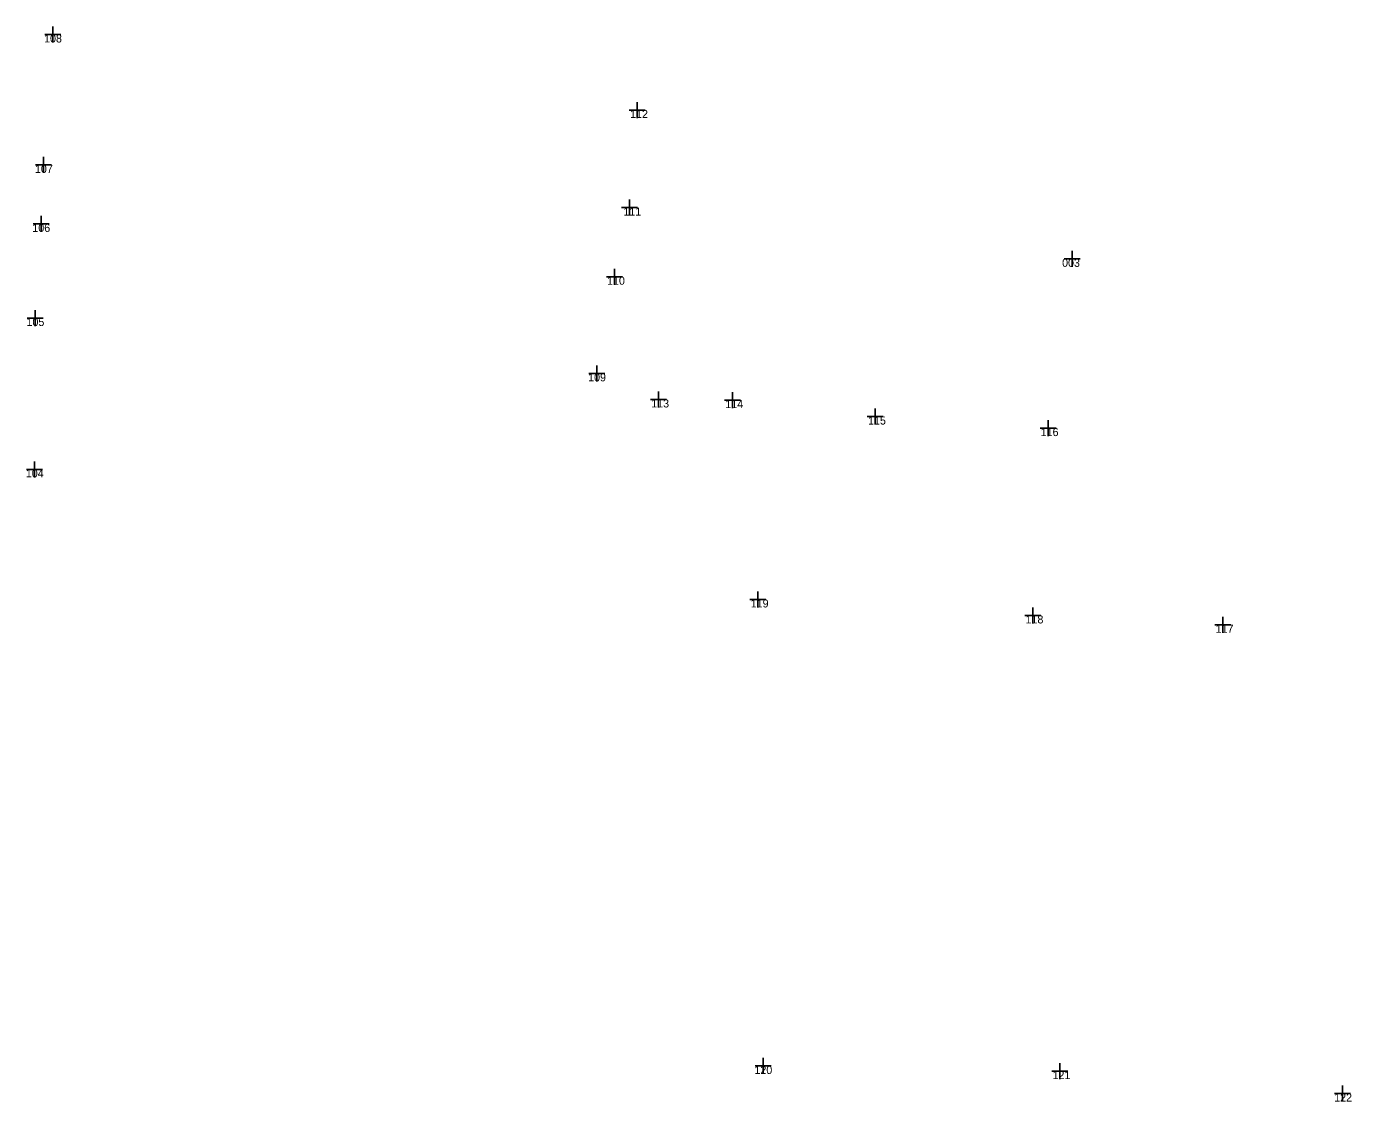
# Model space of a CAD drawing. Extents: x -706655 to -706193, y -1036183 to -1034979.
# Drawn here: x -706282.4 to -706199.6, y -1035570.8 to -1035503.7 of the extents above; entities that cross this region are included whole.
import ezdxf

# ---------------------------------------------------------------- set-up
doc = ezdxf.new("R2010")
doc.units = 0
doc.layers.add('čísla bodu', color=7, linetype='Continuous')

msp = doc.modelspace()

# ---------------------------------------------------------------- linework, layer by layer
at = {"layer": 'čísla bodu'}
for p, q in [((-706281.25, -1035504.15), (-706280.25, -1035504.15)), ((-706280.75, -1035504.65), (-706280.75, -1035503.65)), ((-706280.75, -1035504.15), (-706280.75, -1035504.15)), ((-706244.22, -1035509.37), (-706244.22, -1035508.37)), ((-706244.72, -1035508.87), (-706243.72, -1035508.87)), ((-706244.22, -1035508.87), (-706244.22, -1035508.87)), ((-706281.82, -1035512.3), (-706280.82, -1035512.3)), ((-706281.32, -1035512.8), (-706281.32, -1035511.8)), ((-706281.32, -1035512.3), (-706281.32, -1035512.3)), ((-706245.21, -1035514.97), (-706244.21, -1035514.97)), ((-706244.71, -1035515.47), (-706244.71, -1035514.47)), ((-706244.71, -1035514.97), (-706244.71, -1035514.97)), ((-706281.47, -1035516.49), (-706281.47, -1035515.49)), ((-706281.97, -1035515.99), (-706280.97, -1035515.99)), ((-706281.47, -1035515.99), (-706281.47, -1035515.99)), ((-706217.54, -1035518.17), (-706216.54, -1035518.17)), ((-706217.04, -1035518.67), (-706217.04, -1035517.67)), ((-706217.04, -1035518.17), (-706217.04, -1035518.17)), ((-706245.64, -1035519.79), (-706245.64, -1035518.79)), ((-706246.14, -1035519.29), (-706245.14, -1035519.29)), ((-706245.64, -1035519.29), (-706245.64, -1035519.29)), ((-706281.85, -1035522.37), (-706281.85, -1035521.37)), ((-706282.35, -1035521.87), (-706281.35, -1035521.87)), ((-706281.85, -1035521.87), (-706281.85, -1035521.87)), ((-706246.75, -1035525.83), (-706246.75, -1035524.83)), ((-706247.25, -1035525.33), (-706246.25, -1035525.33)), ((-706246.75, -1035525.33), (-706246.75, -1035525.33)), ((-706242.9, -1035527.46), (-706242.9, -1035526.46)), ((-706238.27, -1035527.5), (-706238.27, -1035526.5)), ((-706243.4, -1035526.96), (-706242.4, -1035526.96)), ((-706242.9, -1035526.96), (-706242.9, -1035526.96)), ((-706238.77, -1035527), (-706237.77, -1035527)), ((-706238.27, -1035527), (-706238.27, -1035527)), ((-706229.85, -1035528.03), (-706228.85, -1035528.03)), ((-706229.35, -1035528.53), (-706229.35, -1035527.53)), ((-706229.35, -1035528.03), (-706229.35, -1035528.03)), ((-706218.55, -1035529.25), (-706218.55, -1035528.25)), ((-706219.05, -1035528.75), (-706218.05, -1035528.75)), ((-706218.55, -1035528.75), (-706218.55, -1035528.75)), ((-706282.39, -1035531.33), (-706281.39, -1035531.33)), ((-706281.89, -1035531.83), (-706281.89, -1035530.83)), ((-706281.89, -1035531.33), (-706281.89, -1035531.33)), ((-706236.68, -1035539.96), (-706236.68, -1035538.96)), ((-706237.18, -1035539.46), (-706236.18, -1035539.46)), ((-706236.68, -1035539.46), (-706236.68, -1035539.46)), ((-706220.01, -1035540.46), (-706219.01, -1035540.46)), ((-706219.51, -1035540.96), (-706219.51, -1035539.96)), ((-706219.51, -1035540.46), (-706219.51, -1035540.46)), ((-706207.63, -1035541.54), (-706207.63, -1035540.54)), ((-706208.13, -1035541.04), (-706207.13, -1035541.04)), ((-706207.63, -1035541.04), (-706207.63, -1035541.04)), ((-706236.86, -1035568.62), (-706235.86, -1035568.62)), ((-706236.36, -1035569.12), (-706236.36, -1035568.12)), ((-706236.36, -1035568.62), (-706236.36, -1035568.62)), ((-706217.82, -1035569.44), (-706217.82, -1035568.44)), ((-706218.32, -1035568.94), (-706217.32, -1035568.94)), ((-706217.82, -1035568.94), (-706217.82, -1035568.94)), ((-706200.65, -1035570.34), (-706199.65, -1035570.34)), ((-706200.15, -1035570.84), (-706200.15, -1035569.84)), ((-706200.15, -1035570.34), (-706200.15, -1035570.34))]:
    msp.add_line(p, q, dxfattribs=at)

# ---------------------------------------------------------------- texts
for s, p in [('108', (-706281.291, -1035504.65)), ('112', (-706244.669, -1035509.37)), ('107', (-706281.861, -1035512.8)), ('111', (-706245.09, -1035515.47)), ('106', (-706282.025, -1035516.49)), ('003', (-706217.674, -1035518.67)), ('110', (-706246.11, -1035519.79)), ('105', (-706282.391, -1035522.37)), ('109', (-706247.293, -1035525.83)), ('113', (-706243.349, -1035527.46)), ('114', (-706238.719, -1035527.5)), ('115', (-706229.799, -1035528.53)), ('116', (-706219.012, -1035529.25)), ('104', (-706282.431, -1035531.83)), ('119', (-706237.131, -1035539.96)), ('118', (-706219.959, -1035540.96)), ('117', (-706208.079, -1035541.54)), ('120', (-706236.901, -1035569.12)), ('121', (-706218.27, -1035569.44)), ('122', (-706200.67, -1035570.84))]:
    msp.add_text(s, height=0.5, dxfattribs=at).set_placement(p)

doc.saveas('drawing.dxf')
